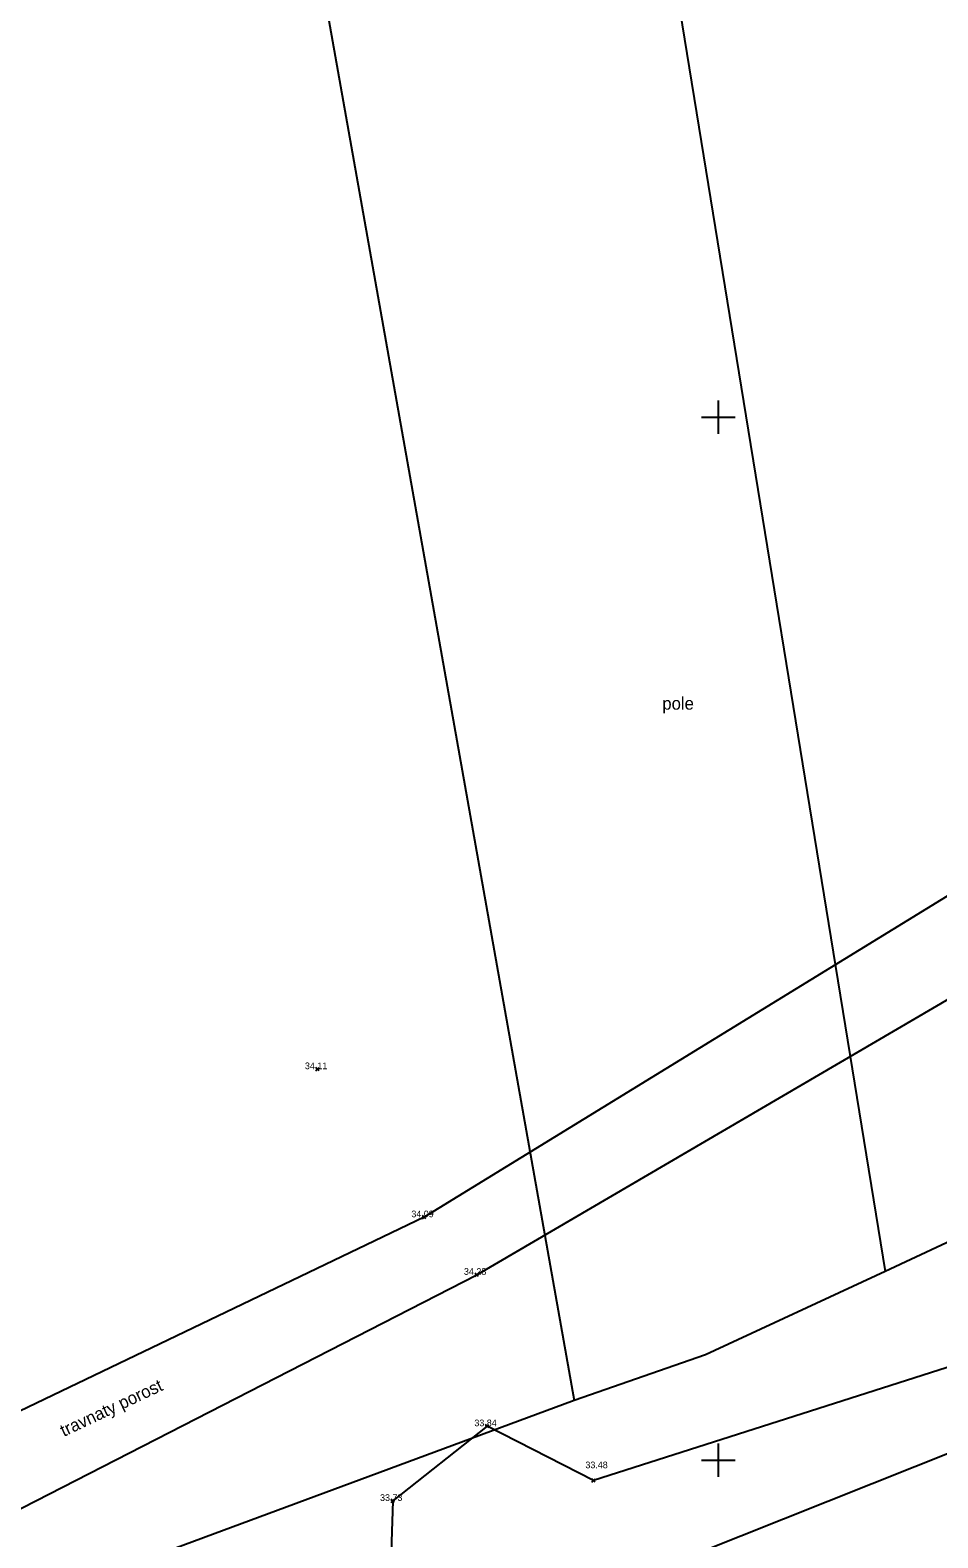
# Model space of a CAD drawing. Extents: x -772865 to -772533, y -1034366 to -1034132.
# Drawn here: x -772791.49 to -772769.74, y -1034276.87 to -1034240.72 of the extents above; entities that cross this region are included whole.
import ezdxf

# ---------------------------------------------------------------- set-up
doc = ezdxf.new("R2010")
doc.units = 0
for name, color, linetype in [('body', 7, 'Continuous'), ('KM_hranice', 7, 'Continuous'), ('mistni_popis', 7, 'Continuous'), ('oddeleni_ploch', 7, 'Continuous'), ('souradnicova_sit', 7, 'Continuous'), ('stromy_kere', 7, 'Continuous'), ('vyskove_koty', 7, 'Continuous')]:
    doc.layers.add(name, color=color, linetype=linetype)

msp = doc.modelspace()

# ---------------------------------------------------------------- linework, layer by layer
at = {"layer": 'body'}
for p, q in [((-772784.56, -1034265.67), (-772784.64, -1034265.59)), ((-772784.64, -1034265.67), (-772784.56, -1034265.59)), ((-772782.01, -1034269.22), (-772782.09, -1034269.14)), ((-772782.09, -1034269.22), (-772782.01, -1034269.14)), ((-772780.75, -1034270.6), (-772780.83, -1034270.52)), ((-772780.83, -1034270.6), (-772780.75, -1034270.52)), ((-772780.5, -1034274.23), (-772780.58, -1034274.15)), ((-772780.58, -1034274.23), (-772780.5, -1034274.15)), ((-772777.95, -1034275.53), (-772778.03, -1034275.45)), ((-772778.03, -1034275.53), (-772777.95, -1034275.45)), ((-772782.76, -1034276.02), (-772782.84, -1034275.94)), ((-772782.84, -1034276.02), (-772782.76, -1034275.94))]:
    msp.add_line(p, q, dxfattribs=at)
at = {"layer": 'KM_hranice'}
for p, q in [((-772789.48, -1034211.5), (-772778.45, -1034273.57)), ((-772780.36, -1034212.98), (-772771, -1034270.48)), ((-772755.58, -1034263.23), (-772771, -1034270.48)), ((-772771, -1034270.48), (-772775.31, -1034272.48)), ((-772775.31, -1034272.48), (-772778.45, -1034273.57)), ((-772778.45, -1034273.57), (-772798.72, -1034281.08))]:
    msp.add_line(p, q, dxfattribs=at)
at = {"layer": 'oddeleni_ploch'}
for points in [[(-772574.1, -1034196.14), (-772586.87, -1034201.34), (-772598.23, -1034205.06), (-772614.53, -1034207.42), (-772626.93, -1034206.95), (-772636.66, -1034207.26), (-772647.96, -1034208.36), (-772659.39, -1034213.08), (-772672.58, -1034218.62), (-772687.49, -1034225.14), (-772703.01, -1034232.02), (-772714.35, -1034236.9), (-772728.88, -1034243.07), (-772737.97, -1034245.74), (-772746.8, -1034246.99), (-772753.85, -1034250.11), (-772762.71, -1034257.3), (-772782.05, -1034269.18), (-772797.09, -1034276.39), (-772810.61, -1034282.39), (-772816.13, -1034284.08), (-772822.76, -1034283.4), (-772826.73, -1034280.27)], [(-772569.67, -1034207.72), (-772578.35, -1034211.18), (-772588.33, -1034216.15), (-772592.11, -1034217.46), (-772598.89, -1034219.1), (-772610.21, -1034219.57), (-772621.14, -1034219.48), (-772637.34, -1034221.06), (-772647.54, -1034222.08), (-772674.34, -1034233.24), (-772685.01, -1034239.21), (-772697.33, -1034242.95), (-772712.12, -1034249.56), (-772725.85, -1034254.8), (-772738.85, -1034261.98), (-772750.37, -1034267.76), (-772764, -1034272.65), (-772783.9, -1034280.59), (-772796.38, -1034286.28), (-772810.31, -1034291.67), (-772823.61, -1034294.35), (-772828.52, -1034296.12), (-772827.01, -1034302.81), (-772823.23, -1034300.75)]]:
    msp.add_lwpolyline(points, dxfattribs=at)
at = {"layer": 'souradnicova_sit'}
for p, q in [((-772775, -1034249.6), (-772775, -1034250.4)), ((-772775.4, -1034250), (-772774.6, -1034250)), ((-772775, -1034274.6), (-772775, -1034275.4)), ((-772775.4, -1034275), (-772774.6, -1034275))]:
    msp.add_line(p, q, dxfattribs=at)
at = {"layer": 'stromy_kere'}
msp.add_line((-772780.79, -1034270.56), (-772765.65, -1034261.7), dxfattribs=at)
for points in [[(-772697.8, -1034241.28), (-772703.73, -1034242.07), (-772708.05, -1034246.5), (-772725.99, -1034253.12), (-772730.64, -1034252.64), (-772736.35, -1034255.43), (-772738.23, -1034258.84), (-772742.19, -1034258.97), (-772751.86, -1034263.8), (-772757.95, -1034266.78), (-772758.48, -1034269.42), (-772764.72, -1034271.25), (-772777.99, -1034275.49), (-772780.54, -1034274.19), (-772782.8, -1034275.98), (-772782.89, -1034278.68), (-772790.87, -1034282.58), (-772810.31, -1034291.67)], [(-772792.97, -1034276.8), (-772780.79, -1034270.56)]]:
    msp.add_lwpolyline(points, dxfattribs=at)

# ---------------------------------------------------------------- texts
at = {"layer": 'mistni_popis'}
msp.add_text('pole', height=0.3, dxfattribs=at).set_placement((-772776.343, -1034257.011))
msp.add_text('travnaty porost', height=0.3, rotation=25.2101, dxfattribs=at).set_placement((-772790.682, -1034274.447))
at = {"layer": 'vyskove_koty'}
for s, p in [('34.11', (-772784.905, -1034265.63)), ('34.09', (-772782.355, -1034269.18)), ('34.28', (-772781.095, -1034270.56)), ('33.84', (-772780.845, -1034274.19)), ('33.48', (-772778.185, -1034275.197)), ('33.73', (-772783.105, -1034275.98))]:
    msp.add_text(s, height=0.16, dxfattribs=at).set_placement(p)

doc.saveas('drawing.dxf')
